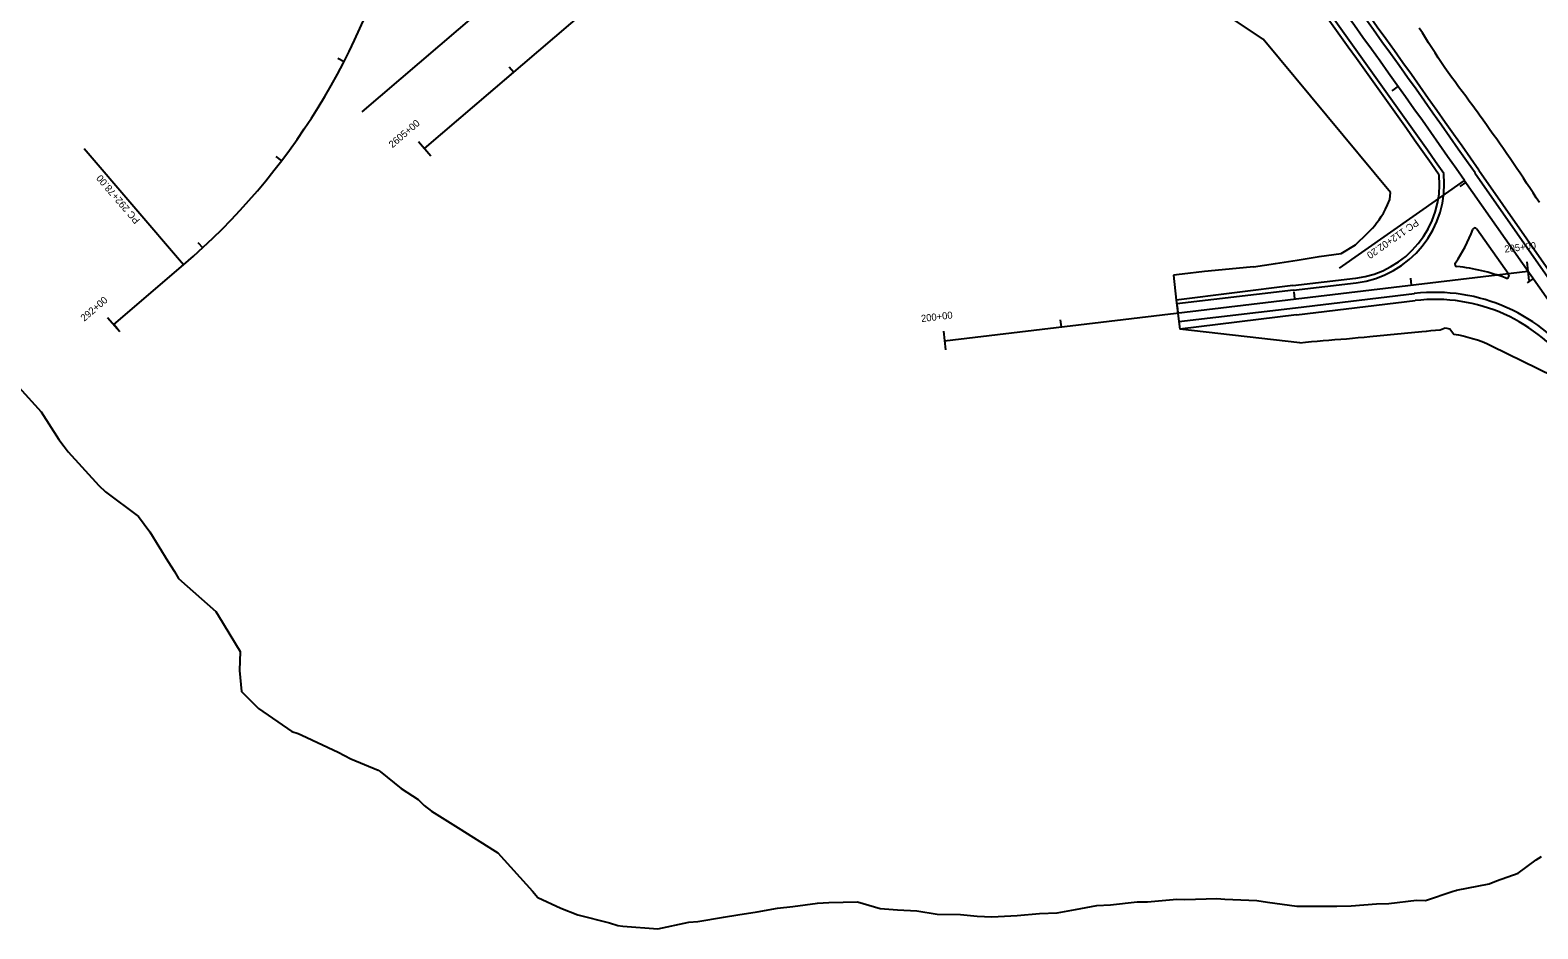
# Model space of a CAD drawing. Extents: x 916431 to 921570, y 1763982 to 1768032.
# Drawn here: x 918187 to 919470, y 1763991 to 1764755 of the extents above; entities that cross this region are included whole.
import ezdxf

# ---------------------------------------------------------------- set-up
doc = ezdxf.new("R2010")
doc.units = 0
for name, color, linetype in [('Default', 7, 'Continuous'), ('R_Horz Alg', 7, 'Continuous'), ('R_Horz Alg Annot', 7, 'Continuous'), ('R_Horz Alg Stationing', 7, 'Continuous'), ('R_Proposed Const Limits', 7, 'Continuous'), ('R_Proposed Road', 7, 'Continuous'), ('R_SFHA', 7, 'Continuous'), ('R_Shld', 7, 'Continuous')]:
    doc.layers.add(name, color=color, linetype=linetype)

msp = doc.modelspace()

# ---------------------------------------------------------------- linework, layer by layer
at = {"layer": 'Default'}
msp.add_line((918522.7, 1764654.5), (918598.6, 1764719.5), dxfattribs=at)
at = {"layer": 'R_Horz Alg'}
for p, q in [((918522.7, 1764654.5), (919661.8, 1765630.4)), ((919553.6, 1764418.8), (919407.5, 1764627.4)), ((918258.1, 1764504.9), (918317.4, 1764555.6)), ((918965.1, 1764491.1), (919461.6, 1764550.2))]:
    msp.add_line(p, q, dxfattribs=at)
for centre, radius, start, end in [((910020.7, 1758054.9), 11459.2, 34.99917, 38.97694), ((917944.6, 1764990.7), 573, 310.5864, 20.6439)]:
    msp.add_arc(centre, radius, start, end, dxfattribs=at)
at = {"layer": 'R_Horz Alg Annot'}
msp.add_line((918622.4, 1764816.9), (918469.3, 1764685.7), dxfattribs=at)
for points in [[(918317.4, 1764555.6), (918232.8, 1764654.3)], [(919407.5, 1764627.4), (919301.1, 1764552.9)]]:
    msp.add_lwpolyline(points, dxfattribs=at)
at = {"layer": 'R_Horz Alg Stationing'}
for points in [[(918448.8, 1764731.5), (918454.1, 1764728.7)], [(918594.7, 1764724.1), (918598.6, 1764719.5)], [(919346.2, 1764703.8), (919351.1, 1764707.3)], [(918517.5, 1764660.5), (918527.9, 1764648.4)], [(918396.1, 1764647.8), (918400.9, 1764644.2)], [(919403.9, 1764622.2), (919408.8, 1764625.6)], [(918329.7, 1764574.6), (918333.8, 1764570.2)], [(919460.7, 1764558.2), (919462.5, 1764542.3)], [(919361.6, 1764544.4), (919362.3, 1764538.4)], [(919461.3, 1764540.3), (919466.2, 1764543.7)], [(919262.3, 1764532.6), (919263, 1764526.6)], [(919163, 1764520.7), (919163.7, 1764514.8)], [(918252.9, 1764510.9), (918263.3, 1764498.8)], [(919063.7, 1764508.9), (919064.4, 1764502.9)], [(918964.2, 1764499.1), (918966.1, 1764483.2)]]:
    msp.add_lwpolyline(points, dxfattribs=at)
at = {"layer": 'R_Proposed Const Limits'}
for p, q in [((919236.4, 1764747.6), (919192.3, 1764776.9)), ((919344.6, 1764617.3), (919236.4, 1764747.6)), ((919267.4, 1764489.4), (919165.4, 1764501))]:
    msp.add_line(p, q, dxfattribs=at)
for points in [[(919471.4, 1764608.6), (919468.7, 1764612.7), (919466, 1764616.9), (919463.3, 1764621), (919463.2, 1764621.1), (919460.5, 1764625.2), (919457.8, 1764629.4), (919455, 1764633.6), (919452.2, 1764637.7), (919449.4, 1764641.9), (919448.8, 1764642.7), (919446.6, 1764646), (919443.7, 1764650.1), (919440.9, 1764654.2), (919438.8, 1764657.1), (919438, 1764658.3), (919435.1, 1764662.4), (919432.2, 1764666.5), (919429.3, 1764670.6), (919426.4, 1764674.7), (919423.5, 1764678.8), (919420.5, 1764682.9), (919418.7, 1764685.4), (919417.6, 1764686.9), (919414.7, 1764691), (919411.7, 1764695), (919408.7, 1764699.1), (919405.7, 1764703.1), (919402.7, 1764707.2), (919399.8, 1764711.2), (919396.7, 1764715.2), (919393.7, 1764719.2), (919390.9, 1764723.3), (919388.1, 1764727.6), (919385.4, 1764731.8), (919382.7, 1764736), (919379.9, 1764740.2), (919377.1, 1764744.4), (919374.5, 1764748.7), (919371.8, 1764752.9), (919369.1, 1764757.1)], [(919325, 1764582.5), (919327.2, 1764584.6), (919329.3, 1764586.8), (919331.3, 1764589.1), (919333.2, 1764591.5), (919335, 1764594), (919336.8, 1764596.8), (919338.6, 1764599.7), (919340.4, 1764602.9), (919342.2, 1764606.6), (919344, 1764611.2), (919344.6, 1764617.3)], [(919228.2, 1764554), (919246.8, 1764556.9), (919265.4, 1764559.7), (919284.1, 1764562.6), (919302.7, 1764565.4), (919314.9, 1764572.7), (919325, 1764582.5)], [(919228.2, 1764554), (919207.3, 1764552), (919186.5, 1764550), (919167.4, 1764547.7), (919159.9, 1764546.8)], [(919159.9, 1764546.8), (919162.4, 1764525.6)], [(919267.4, 1764489.4), (919272.4, 1764489.8), (919277.4, 1764490.3), (919282.4, 1764490.8), (919287.4, 1764491.2), (919292.3, 1764491.6), (919297.3, 1764492), (919302.3, 1764492.4), (919307.3, 1764492.8), (919312.3, 1764493.2), (919317.3, 1764493.7), (919322.3, 1764494.1), (919327.2, 1764494.6), (919371.4, 1764498.8)], [(919371.4, 1764498.8), (919375.2, 1764499.3), (919379.1, 1764499.7), (919383.1, 1764500), (919387.1, 1764500.3), (919391.2, 1764501.9)], [(919391.2, 1764501.9), (919395.2, 1764501.1)], [(919395.2, 1764501.1), (919398.7, 1764496.7), (919402.7, 1764496.1), (919406.6, 1764495.3), (919410.6, 1764494.1), (919414.6, 1764493), (919418.6, 1764491.7), (919422.6, 1764490.3), (919426.6, 1764488.6), (919430.7, 1764486.8), (919483.3, 1764460.9)]]:
    msp.add_lwpolyline(points, dxfattribs=at)
at = {"layer": 'R_Proposed Road'}
for p, q in [((919416.6, 1764633.8), (919478.5, 1764545.2)), ((919445.3, 1764547.4), (919418.2, 1764586.1)), ((919262.1, 1764534), (919162.8, 1764522.4)), ((919262.1, 1764534), (919315.5, 1764540.4)), ((919263.9, 1764519.1), (919365, 1764531.2)), ((919162.4, 1764525.6), (919165.4, 1764501)), ((919164.6, 1764507.3), (919263.9, 1764519.1))]:
    msp.add_line(p, q, dxfattribs=at)
for centre, radius, start, end in [((910020.7, 1758054.9), 11470.2, 34.99917, 38.97694), ((910020.7, 1758054.9), 11448.2, 35.07322, 38.97694), ((919305.5, 1764624.8), 85, 276.7925, 5.7051), ((919305.5, 1764624.8), 116, 324.4663, 340.271), ((919416.5, 1764585), 2, 34.9992, 160.271), ((919401.5, 1764556.2), 2, 144.4663, 263.8361), ((919382.7, 1764382.2), 173, 69.6273, 83.8361), ((919443.6, 1764546.3), 2, 249.6273, 34.9992), ((919382.7, 1764382.2), 150, 34.9992, 96.7925)]:
    msp.add_arc(centre, radius, start, end, dxfattribs=at)
at = {"layer": 'R_SFHA'}
msp.add_lwpolyline([(918177.3, 1764451.5), (918196.3, 1764430.5), (918211.3, 1764406.9), (918215.8, 1764401.1), (918219.3, 1764396.5), (918245.3, 1764367.9), (918251.2, 1764362.6), (918279.3, 1764341.6), (918288.9, 1764328.6), (918304.2, 1764303.6), (918309.8, 1764294.6), (918313.3, 1764288.7), (918345.1, 1764260.6), (918347.3, 1764257.1), (918365.6, 1764226.6), (918365.2, 1764210.6), (918366.8, 1764192.6), (918381.3, 1764178.2), (918409.7, 1764158.6), (918415.2, 1764156.9), (918418.3, 1764155.6), (918449.2, 1764141), (918460, 1764135.4), (918483.2, 1764125.8), (918484.8, 1764124.6), (918502.6, 1764110.1), (918517.2, 1764100.7), (918522.2, 1764095.7), (918528.6, 1764090.7), (918551.2, 1764076.6), (918582.8, 1764056.7), (918585.1, 1764055.3), (918614.6, 1764022.7), (918619.1, 1764017.4), (918638.7, 1764008.2), (918653.1, 1764002.6), (918680, 1763995.8), (918687.1, 1763993.6), (918691.4, 1763993), (918721.1, 1763990.7), (918747.4, 1763996.4), (918755.1, 1763996.9), (918777, 1764000.7), (918789.1, 1764002.5), (918805.6, 1764005.3), (918823, 1764008.2), (918836, 1764009.8), (918857.1, 1764012.5), (918866.6, 1764013.1), (918891, 1764013.8), (918910.5, 1764008.1), (918925, 1764007), (918941.7, 1764006), (918959, 1764003.1), (918978.7, 1764003), (918993, 1764001.5), (919005.3, 1764001), (919027, 1764002.1), (919045.9, 1764003.8), (919061, 1764004.3), (919076.5, 1764007.1), (919094.9, 1764010.6), (919106.4, 1764011.2), (919129, 1764013.7), (919137.8, 1764013.8), (919162.9, 1764016), (919169.8, 1764015.8), (919196.9, 1764016.4), (919203.6, 1764016), (919230.9, 1764014.8), (919240.1, 1764013.5), (919264.9, 1764010), (919277.7, 1764009.9), (919298.9, 1764009.9), (919311.2, 1764010.3), (919332.8, 1764011.9), (919343.2, 1764012.3), (919366.8, 1764015.2), (919374.6, 1764014.8), (919398, 1764022.7), (919400.2, 1764023.3), (919400.8, 1764023.7), (919428.6, 1764028.9), (919434.8, 1764031.6), (919453.3, 1764038.2), (919468.8, 1764049.3), (919473.3, 1764052.2)], dxfattribs=at)
at = {"layer": 'R_Shld'}
for p, q in [((919419.8, 1764636.1), (919481.2, 1764548.5)), ((919261.6, 1764538), (919315, 1764544.4)), ((919261.7, 1764538), (919162.4, 1764525.6)), ((919264.6, 1764513.2), (919365.7, 1764525.2)), ((918261.4, 1764501.1), (918258.1, 1764504.9)), ((919264.6, 1764513.2), (919165.4, 1764501))]:
    msp.add_line(p, q, dxfattribs=at)
for centre, radius, start, end in [((910020.7, 1758054.9), 11474.2, 34.99917, 38.97694), ((910020.7, 1758054.9), 11444.2, 35.07854, 38.97694), ((919305.5, 1764624.8), 81, 276.7925, 4.9719), ((919382.7, 1764382.2), 144, 34.9992, 96.7925)]:
    msp.add_arc(centre, radius, start, end, dxfattribs=at)

# ---------------------------------------------------------------- texts
at = {"layer": 'R_Horz Alg Annot'}
for s, rotation, p in [('PC 292+78.00', 130.5864, (918280.8, 1764593.7)), ('PC 112+02.20', 214.9992, (919366.1, 1764594.8))]:
    msp.add_text(s, height=6, rotation=rotation, dxfattribs=at).set_placement(p)
at = {"layer": 'R_Horz Alg Stationing'}
for s, rotation, p in [('2605+00', 40.5864, (918495.3, 1764654.7)), ('205+00', 6.7925, (919442, 1764566)), ('292+00', 40.5864, (918233, 1764507.1)), ('200+00', 6.7925, (918945.5, 1764506.9))]:
    msp.add_text(s, height=6, rotation=rotation, dxfattribs=at).set_placement(p)

doc.saveas('drawing.dxf')
